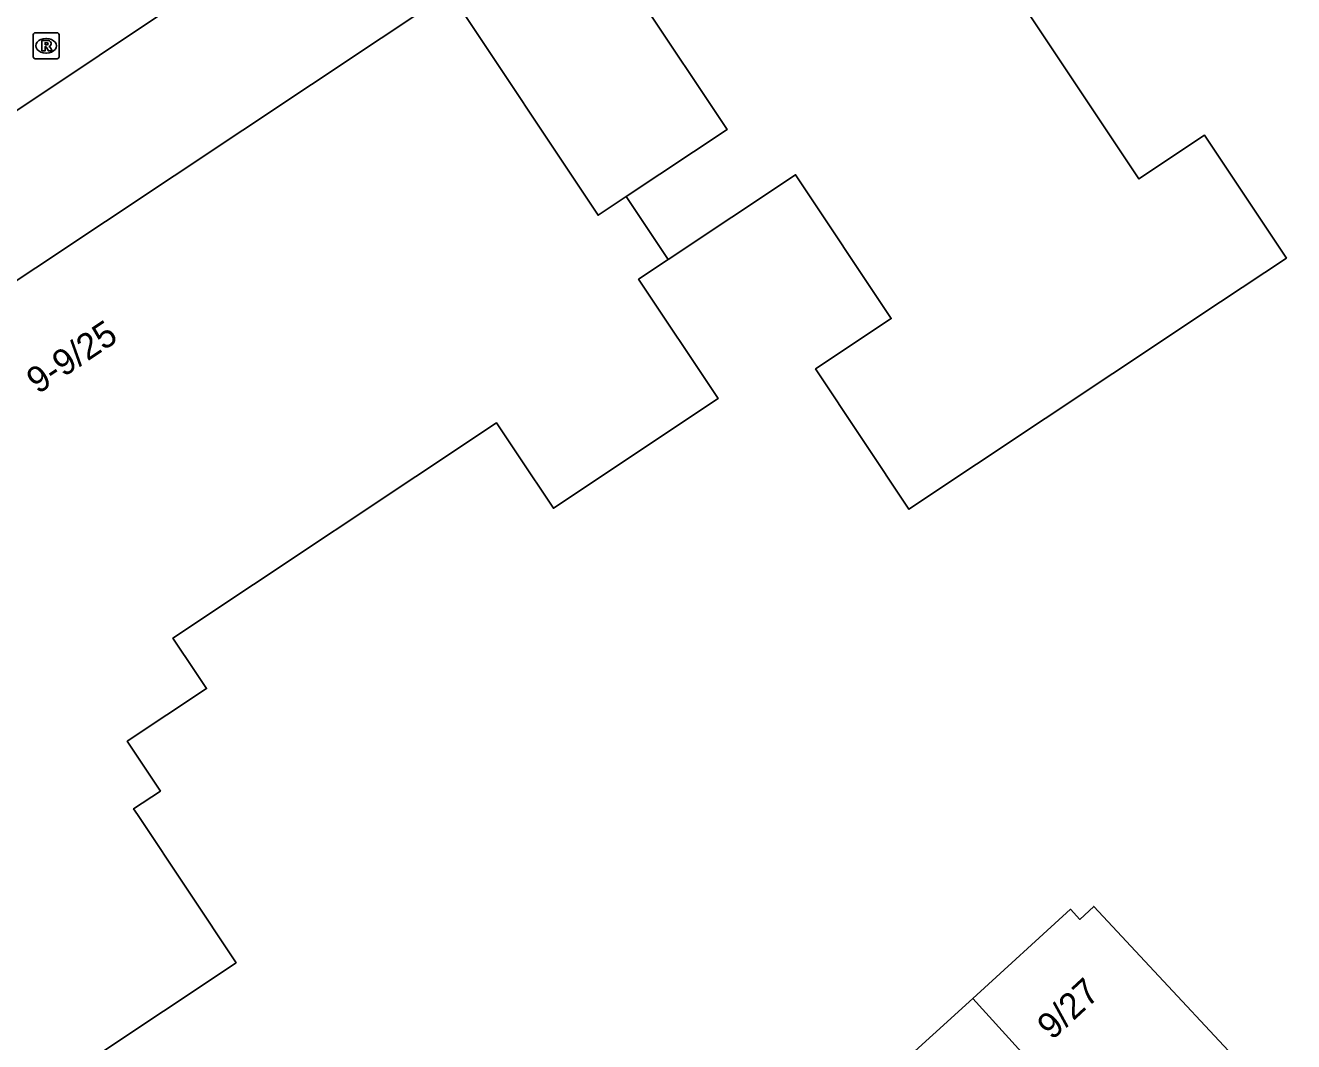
# Model space of a CAD drawing. Extents: x 161354 to 161876, y 382161 to 382804.
# Drawn here: x 161609.6 to 161658.58, y 382580.37 to 382619.62 of the extents above; entities that cross this region are included whole.
import ezdxf

# ---------------------------------------------------------------- set-up
doc = ezdxf.new("R2010")
doc.units = 0
for name, color, linetype in [('IMGEO_Pand', 7, 'Continuous'), ('IMGEO_Pand_nummerreeks', 7, 'Continuous'), ('IMGEO_Rioolput', 7, 'Continuous'), ('IMGEO_Voetpad_open', 7, 'Continuous')]:
    doc.layers.add(name, color=color, linetype=linetype)

msp = doc.modelspace()

# ---------------------------------------------------------------- linework, layer by layer
at = {"layer": 'IMGEO_Pand'}
for points in [[(161632.808, 382613.004), (161636.704, 382615.596), (161633.373, 382620.601), (161636.145, 382622.446), (161634.617, 382624.742), (161643.428, 382630.605), (161645.338, 382627.735), (161645.942, 382628.137), (161648.492, 382624.305), (161648.516, 382623.924), (161646.628, 382622.668), (161652.605, 382613.685), (161655.144, 382615.375), (161658.302, 382610.63), (161655.763, 382608.94), (161651.601, 382606.171), (161643.724, 382600.93), (161640.118, 382606.349), (161643.044, 382608.296), (161639.351, 382613.846), (161634.428, 382610.57)], [(161607.344, 382608.485), (161625.993, 382620.895), (161631.724, 382612.283), (161632.808, 382613.004)], [(161634.428, 382610.57), (161632.808, 382613.004)], [(161634.428, 382610.57), (161633.287, 382609.811), (161636.354, 382605.203), (161629.995, 382600.972), (161628.62, 382603.038), (161627.798, 382604.273), (161615.304, 382595.959), (161616.185, 382594.634), (161616.602, 382594.008), (161613.542, 382591.971), (161614.821, 382590.05), (161613.787, 382589.363), (161613.931, 382589.146), (161615.901, 382586.187), (161617.744, 382583.418), (161609.323, 382577.814)], [(161646.188, 382582.043), (161649.968, 382585.484), (161650.322, 382585.095), (161650.859, 382585.596), (161658.581, 382577.332), (161654.132, 382573.291)], [(161642.757, 382578.236), (161643.428, 382578.834), (161643.099, 382579.23), (161646.188, 382582.043)], [(161646.188, 382582.043), (161654.132, 382573.291)]]:
    msp.add_lwpolyline(points, dxfattribs=at)
at = {"layer": 'IMGEO_Rioolput'}
for p, q in [((161609.983, 382619.33), (161610.835, 382619.33)), ((161609.908, 382618.404), (161609.908, 382619.256)), ((161610.396, 382619.11), (161610.421, 382619.11)), ((161610.909, 382619.256), (161610.909, 382618.404)), ((161610.835, 382618.33), (161609.983, 382618.33)), ((161610.419, 382618.55), (161610.394, 382618.55))]:
    msp.add_line(p, q, dxfattribs=at)
for points in [[(161609.983, 382619.33), (161610.835, 382619.33)], [(161609.908, 382618.404), (161609.908, 382619.256)], [(161610.497, 382619.028), (161610.245, 382619.03), (161610.245, 382618.63)], [(161610.423, 382618.949), (161610.369, 382618.949), (161610.369, 382618.868)], [(161610.369, 382618.868), (161610.421, 382618.868)], [(161610.909, 382619.256), (161610.909, 382618.404)], [(161610.835, 382618.33), (161609.983, 382618.33)], [(161610.245, 382618.63), (161610.369, 382618.63), (161610.369, 382618.792), (161610.38, 382618.792)], [(161610.427, 382618.763), (161610.498, 382618.63), (161610.638, 382618.63), (161610.573, 382618.756)]]:
    msp.add_lwpolyline(points, dxfattribs=at)
for centre, radius, start, end in [((161609.985, 382619.254), 0.0765, 91.552, 178.448), ((161609.985, 382619.254), 0.0765, 91.552, 178.448), ((161610.833, 382619.254), 0.0765, 1.552, 88.448), ((161610.833, 382619.254), 0.0765, 1.552, 88.448), ((161610.405, 382619.057), 0.19, 274.7715, 282.9687), ((161610.429, 382618.853), 0.0964, 77.0061, 93.1865), ((161610.443, 382618.91), 0.0378, 276.6634, 79.6772), ((161610.496, 382618.918), 0.109, 350.3612, 89.416), ((161610.494, 382618.918), 0.112, 277.5842, 350.9817), ((161610.478, 382618.703), 0.108, 29.5134, 73.7905), ((161609.985, 382618.406), 0.0765, 181.552, 268.448), ((161609.985, 382618.406), 0.0765, 181.552, 268.448), ((161610.379, 382618.739), 0.0533, 26.0293, 88.6989), ((161610.833, 382618.406), 0.0765, 271.552, 358.448), ((161610.833, 382618.406), 0.0765, 271.552, 358.448)]:
    msp.add_arc(centre, radius, start, end, dxfattribs=at)
for centre, major_axis, ratio, start_param, end_param in [((161610.395, 382618.83), (-0.387, 0.002), 0.722429, 4.712389, 7.853982), ((161610.42, 382618.83), (-0.39, 0.002), 0.717154, 1.570796, 4.712389)]:
    msp.add_ellipse(centre, major_axis=major_axis, ratio=ratio, start_param=start_param, end_param=end_param, dxfattribs=at)
at = {"layer": 'IMGEO_Voetpad_open'}
msp.add_lwpolyline([(161642.272, 382638.554), (161626.724, 382627.988), (161591.014, 382604.147)], dxfattribs=at)

# ---------------------------------------------------------------- texts
at = {"layer": 'IMGEO_Pand_nummerreeks'}
for s, rotation, p in [('9-9/25', 33.6449, (161610.086, 382605.358)), ('9/27', 42.805, (161649.255, 382580.402))]:
    msp.add_text(s, height=1, rotation=rotation, dxfattribs=at).set_placement(p)

doc.saveas('drawing.dxf')
